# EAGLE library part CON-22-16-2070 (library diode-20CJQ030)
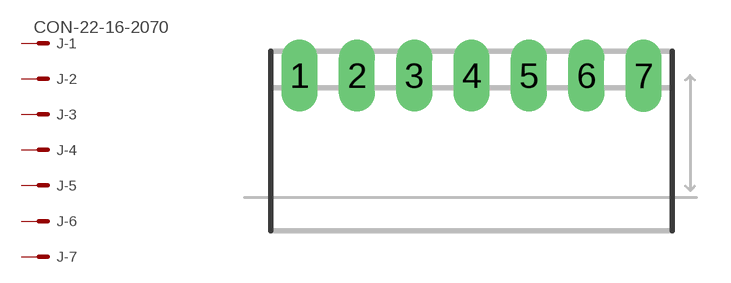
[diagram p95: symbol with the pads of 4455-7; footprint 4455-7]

Designator prefix J; gates -1=MV -2=M -3=M -4=M -5=M -6=M -7=M

## CON-22-16-2070  [4455-7]
1  -1:S  pas
2  -2:S  pas
3  -3:S  pas
4  -4:S  pas
5  -5:S  pas
6  -6:S  pas
7  -7:S  pas

## Footprint 4455-7 (pad centres in mm)
.100" (2.54mm) Center Header - 7 Pin
drill 1.07 long: 1 -7.62,2.4; 2 -5.08,2.4; 3 -2.54,2.4; 4 0,2.4; 5 2.54,2.4; 6 5.08,2.4; 7 7.62,2.39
